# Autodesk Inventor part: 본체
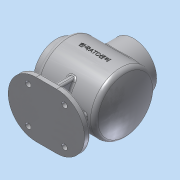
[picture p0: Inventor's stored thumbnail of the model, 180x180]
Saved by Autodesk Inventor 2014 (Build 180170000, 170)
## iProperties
Created: 2023-01
Part Number: 본체
Material: 알루미늄 6061
Document SubType Name: Modeling
Designer: dg
Density: 2.71 g/cm^3
Appearance: 알루미늄 - 평지
Mass: 1038.28 g
Surface Area: 1157.53 cm^2
Volume: 383.128 cm^3
Author: dg
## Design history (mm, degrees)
sketch "스케치1"
  geometry: L1 (0, 0)-(122, 0); L2 (0, 38)-(12, 38); L3 (12, 38)-(12, 50); L4 (12, 50)-(111.087, 50); L5 (0, 38)-(0, 27); L6 (0, 27)-(17, 27); L7 (17, 27)-(17, 45); L8 (17, 45)-(107.83, 45); A1 r 120 centre (2, 0) between (122, 0) and (111.087, 50); A2 r 115 centre (2, 0) between (117, 0) and (107.83, 45)
  constraints: 16 end point, 4 point on circle, 3 parallel, 2 centre point, 2 horizontal alignment, 2 perpendicular, 1 concentric, 1 horizontal, 1 point on line, 1 vertical alignment
  dimensions: "d0" = 122 distance of L1.start L1.end; "d1" = 54 diameter of L6 L1; "d2" = 76 diameter of L2 L1; "d3" = 100 diameter of L4 L1; "d4" = 17 distance of L5.end L6.end; "d5" = 110 horizontal distance of L1.end L3.end; "d6" = 120 radius of A1; "d7" = 90 diameter of L8 L1; "d8" = 5 radial gap between concentric circles of A1 A2
revolve "회전1" sketch "스케치1" stored, may be unused: angle "d9" = 90 deg
fillet "모깎기1" dims "d10" = 8
sketch "스케치2"
  geometry: C1 r 38 at (0, 0) reference; 1 further point
  constraints: 1 vertical alignment
  dimensions: "d11" = 32.5 distance of C1.centre point (0, 32.5)
hole "구멍1" sketch "스케치2" at (0, 32.5) diameter "d12" = 3.242; stored, may be unused: countersink angle "d16" = 90 deg, drill point angle "d18" = 118 deg; dims "d13" = 8, "d14" = 4, "d15" = 2, "d17" = 10
node "작업 평면1"
sketch "스케치3"
  geometry: L1 (0, 38)-(0, -38) reference; C1 r 38 at (-63, 0); A1 r 120 centre (-2, 0) between (-113.243, 45) and (-113.243, -45) reference; 2 further points
  constraints: 1 centre point, 1 horizontal alignment, 1 midpoint
  dimensions: "d23" = 76 diameter of C1; "d24" = 63 distance of point (0, 0) C1.centre
extrude "돌출1" join sketch "스케치3" stored distance "d25" = 10; taper "d26" = 0 deg
sketch "스케치4"
  geometry: C1 r 38 at (0, 0) reference; C2 r 27 at (0, 0); 1 further point
  constraints: 1 centre point, 1 coincident
  dimensions: "d27" = 54 diameter of C2
extrude "돌출2" cut sketch "스케치4" stored distance "d28" = 10; taper "d29" = 0 deg
chamfer "모따기1" distance "d30" = 1; stored, may be unused: second distance "d31" = 2, angle "d32" = 45 deg
sketch "스케치5"
  geometry: C1 r 38 at (0, 0) reference; 2 further points
  constraints: 1 vertical alignment
  dimensions: "d33" = 32.5 distance of C1.centre point (0, 32.5)
hole "구멍2" sketch "스케치5" at (0, 32.5) diameter "d34" = 3.242; stored, may be unused: countersink angle "d38" = 90 deg, drill point angle "d40" = 118 deg; dims "d35" = 8, "d36" = 4, "d37" = 2, "d39" = 10
fillet "모깎기2" dims "d44" = 3
chamfer "모따기2" distance "d45" = 1; stored, may be unused: second distance "d46" = 2, angle "d47" = 45 deg
fillet "모깎기3" dims "d48" = 3
node "작업 평면2"
sketch "스케치6"
  geometry: L1 (0, 38)-(0, -38) reference; L2 (-80, 46)-(-46, 46); L3 (-46, -46)-(-80, -46); L4 (-126, 0)-(0, 0); A1 r 46 centre (-46, 0) between (-46, -46) and (-46, 46); A2 r 46 centre (-80, 0) between (-80, 46) and (-80, -46); 2 further points
  constraints: 6 end point, 6 point on circle, 2 centre point, 2 perpendicular, 2 tangent, 1 coincident, 1 equal radius, 1 horizontal alignment, 1 midpoint, 1 parallel
  dimensions: "d50" = 92 distance between parallel lines of L3 L2; "d51" = 126 distance of L4.start point (0, 0)
extrude "돌출3" join sketch "스케치6" distance "d52" = 10; taper "d53" = 0 deg
sketch "스케치7"
  geometry: L1 (46, -46)-(80, -46) reference; L2 (80, 46)-(46, 46) reference; L3 (63, 46)-(63, -46); C1 r 4.5 at (33, 30); C2 r 4.5 at (33, -30); C3 r 4.5 at (93, -30); C4 r 4.5 at (93, 30); A1 r 46 centre (46, 0) between (46, 46) and (46, -46) reference; 1 further point
  constraints: 4 centre point, 3 equal radius, 2 end point, 2 horizontal alignment, 2 midpoint, 2 vertical alignment
  dimensions: "d54" = 60 distance of C4.centre C1.centre; "d55" = 60 distance of C2.centre C1.centre; "d56" = 30 vertical distance of A1.centre C2.centre; "d57" = 9 diameter of C1; "d58" = 30 distance from line of C4.centre L3
extrude "돌출4" cut sketch "스케치7" stored distance "d59" = 10; taper "d60" = 0 deg
sketch "스케치8"
  geometry: L1 (80, 46)-(46, 46) reference; L2 (58, 35)-(68, 35); L3 (68, 35)-(68, -35); L4 (68, -35)-(58, -35); L5 (58, -35)-(58, 35); A1 r 46 centre (46, 0) between (46, 46) and (46, -46) reference; 5 further points
  constraints: 8 end point, 3 midpoint, 2 parallel, 1 horizontal, 1 horizontal alignment, 1 perpendicular, 1 point on circle, 1 vertical alignment
  dimensions: "d61" = 10 distance of L2.start L2.end; "d62" = 70 distance of L4.end L2.start
extrude "돌출5" join sketch "스케치8" stored distance "d63" = 10; taper "d64" = 0 deg
sketch "스케치9"
  geometry: L1 (10.974, 32.5)-(10, 34.121) reference; L2 (10, 34.121)-(0, 34.121) reference; L3 (0, 34.121)-(0, 38) reference; L4 (0, 38)-(9, 38) reference; L5 (12, 41)-(12, 42) reference; L6 (20, 50)-(22, 50) reference; L7 (25, 53)-(25, 64) reference; L8 (25, 64)-(28.879, 64) reference; L9 (28.879, 64)-(28.879, 54) reference; L10 (28.879, 54)-(30.5, 53.026) reference; L11 (30.5, 53.026)-(32.121, 54) reference; L12 (32.121, 54)-(32.121, 64) reference; L13 (32.121, 64)-(35, 64) reference; L14 (35, 64)-(36, 63) reference; L15 (36, 63)-(36, 45) reference; L16 (36, 45)-(20, 45) reference; L17 (17, 42)-(17, 27) reference; L18 (17, 27)-(1, 27) reference; L19 (1, 27)-(0, 28) reference; L20 (0, 28)-(0, 30.879) reference; L21 (0, 30.879)-(10, 30.879) reference; L22 (10, 30.879)-(10.974, 32.5) reference; L23 (126, -70)-(126, -80) reference; L24 (126, -80)-(0, -80) reference; L25 (0, -80)-(0, -70) reference; L26 (0, -70)-(58, -70) reference; L27 (58, -70)-(58, -50) reference; L28 (58, -50)-(20, -50) reference; L29 (12, -42)-(12, -41) reference; L30 (9, -38)-(0, -38) reference; L31 (0, -38)-(0, -34.121) reference; L32 (0, -34.121)-(10, -34.121) reference; L33 (10, -34.121)-(10.974, -32.5) reference; L34 (10.974, -32.5)-(10, -30.879) reference; L35 (10, -30.879)-(0, -30.879) reference; L36 (0, -30.879)-(0, -28) reference; L37 (0, -28)-(1, -27) reference; L38 (1, -27)-(17, -27) reference; L39 (17, -27)-(17, -42) reference; L40 (20, -45)-(105.827, -45) reference; L41 (105.827, 45)-(90, 45) reference; L42 (90, 45)-(90, 63) reference; L43 (90, 63)-(91, 64) reference; L44 (91, 64)-(93.879, 64) reference; L45 (93.879, 64)-(93.879, 54) reference; L46 (93.879, 54)-(95.5, 53.026) reference; L47 (95.5, 53.026)-(97.121, 54) reference; L48 (97.121, 54)-(97.121, 64) reference; L49 (97.121, 64)-(101, 64) reference; L50 (101, 64)-(101, 53) reference; L51 (104, 50)-(105.827, 50) reference; L52 (105.827, -50)-(68, -50) reference; L53 (68, -50)-(68, -70) reference; L54 (68, -70)-(126, -70) reference; L55 (91, 64)-(35, 64) reference; L56 (63, -80)-(63, 64); L57 (23, -70)-(28.359, -50); A1 r 3 centre (9, 41) between (9, 38) and (12, 41) reference; A2 r 8 centre (20, 42) between (20, 50) and (12, 42) reference; A3 r 3 centre (20, 42) between (20, 45) and (17, 42) reference; A4 r 8 centre (20, -42) between (12, -42) and (20, -50) reference; A5 r 3 centre (9, -41) between (12, -41) and (9, -38) reference; A6 r 3 centre (20, -42) between (17, -42) and (20, -45) reference; A7 r 3 centre (105.827, -42) between (105.827, -45) and (108.608, -43.125) reference; A8 r 115 centre (2, 0) between (108.608, -43.125) and (108.608, 43.125) reference; A9 r 3 centre (105.827, 42) between (108.608, 43.125) and (105.827, 45) reference; A10 r 8 centre (105.827, 42) between (113.243, 45) and (105.827, 50) reference; A11 r 120 centre (2, 0) between (113.243, -45) and (113.243, 45) reference; A12 r 8 centre (105.827, -42) between (105.827, -50) and (113.243, -45) reference; 1 further point
  constraints: 4 end point, 2 midpoint, 2 point on line, 2 other
  dimensions: "d65" = 105 deg angle of L26 L57; "d66" = 40 horizontal distance of L56.start L57.start
feature "리브1" sketch "스케치9" dims "d67" = 1, "d68" = 10, "d69" = 0, "d70" = 0, "d71" = 1, "d72" = 1
sketch "스케치10"
  geometry: L1 (10, -34.121)-(10.974, -32.5) reference; L2 (10.974, -32.5)-(10, -30.879) reference; L3 (10, -30.879)-(0, -30.879) reference; L4 (0, -30.879)-(0, -28) reference; L5 (0, -28)-(1, -27) reference; L6 (1, -27)-(17, -27) reference; L7 (17, -27)-(17, -42) reference; L8 (20, -45)-(105.827, -45) reference; L9 (105.827, 45)-(90, 45) reference; L10 (90, 45)-(90, 63) reference; L11 (90, 63)-(91, 64) reference; L12 (91, 64)-(93.879, 64) reference; L13 (93.879, 64)-(93.879, 54) reference; L14 (93.879, 54)-(95.5, 53.026) reference; L15 (95.5, 53.026)-(97.121, 54) reference; L16 (97.121, 54)-(97.121, 64) reference; L17 (97.121, 64)-(101, 64) reference; L18 (101, 64)-(101, 53) reference; L19 (104, 50)-(105.827, 50) reference; L20 (105.827, -50)-(68, -50) reference; L21 (68, -50)-(68, -70) reference; L22 (68, -70)-(126, -70) reference; L23 (126, -70)-(126, -80) reference; L24 (126, -80)-(0, -80) reference; L25 (0, -80)-(0, -70) reference; L26 (0, -70)-(23, -70) reference; L27 (23, -70)-(28.359, -50) reference; L28 (28.359, -50)-(20, -50) reference; L29 (12, -42)-(12, -41) reference; L30 (9, -38)-(0, -38) reference; L31 (0, -38)-(0, -34.121) reference; L32 (0, -34.121)-(10, -34.121) reference; L33 (10.974, 32.5)-(10, 34.121) reference; L34 (10, 34.121)-(0, 34.121) reference; L35 (0, 34.121)-(0, 38) reference; L36 (0, 38)-(9, 38) reference; L37 (12, 41)-(12, 42) reference; L38 (20, 50)-(22, 50) reference; L39 (25, 53)-(25, 64) reference; L40 (25, 64)-(28.879, 64) reference; L41 (28.879, 64)-(28.879, 54) reference; L42 (28.879, 54)-(30.5, 53.026) reference; L43 (30.5, 53.026)-(32.121, 54) reference; L44 (32.121, 54)-(32.121, 64) reference; L45 (32.121, 64)-(35, 64) reference; L46 (35, 64)-(36, 63) reference; L47 (36, 63)-(36, 45) reference; L48 (36, 45)-(20, 45) reference; L49 (17, 42)-(17, 27) reference; L50 (17, 27)-(1, 27) reference; L51 (1, 27)-(0, 28) reference; L52 (0, 28)-(0, 30.879) reference; L53 (0, 30.879)-(10, 30.879) reference; L54 (10, 30.879)-(10.974, 32.5) reference; L55 (97.641, -50)-(103, -70); L56 (91, 64)-(35, 64) reference; L57 (63, 64)-(63, -80); A1 r 3 centre (20, -42) between (17, -42) and (20, -45) reference; A2 r 3 centre (105.827, -42) between (105.827, -45) and (108.608, -43.125) reference; A3 r 115 centre (2, 0) between (108.608, -43.125) and (108.608, 43.125) reference; A4 r 3 centre (105.827, 42) between (108.608, 43.125) and (105.827, 45) reference; A5 r 8 centre (105.827, 42) between (113.243, 45) and (105.827, 50) reference; A6 r 120 centre (2, 0) between (113.243, -45) and (113.243, 45) reference; A7 r 8 centre (105.827, -42) between (105.827, -50) and (113.243, -45) reference; A8 r 8 centre (20, -42) between (12, -42) and (20, -50) reference; A9 r 3 centre (9, -41) between (12, -41) and (9, -38) reference; A10 r 3 centre (9, 41) between (9, 38) and (12, 41) reference; A11 r 8 centre (20, 42) between (20, 50) and (12, 42) reference; A12 r 3 centre (20, 42) between (20, 45) and (17, 42) reference; 1 further point
  constraints: 4 end point, 2 midpoint, 2 point on line, 2 other
  dimensions: "d73" = 105 deg angle of L22 L55; "d74" = 40 horizontal distance of L55.end L57.end
feature "리브2" sketch "스케치10" dims "d75" = 1, "d76" = 10, "d77" = 0, "d78" = 0, "d79" = 1, "d80" = 1
fillet "모깎기4" dims "d81" = 3
fillet "모깎기5" dims "d82" = 3
node "작업 평면3"
sketch "스케치11"
  geometry: L1 (0, -38)-(0, 38) reference; L2 (97.5, -80)-(88.5, -80) reference; L3 (37.5, -80)-(28.5, -80) reference; L4 (37.5, -80)-(28.5, -80) reference; L5 (97.5, -80)-(88.5, -80) reference; L6 (46, -80)-(46, -80) reference; L7 (46, -80)-(80, -80) reference; L8 (80, -80)-(80, -80) reference; L9 (80, -80)-(46, -80) reference; L10 (80, -80)-(126, -80) reference; 2 further points
  constraints: 1 other
  dimensions: "d84" = 80 distance from line of L10 point (63, 0); "d85" = 63 distance from line of L1 point (63, 0)
feature "엠보싱1" sketch "스케치11" dims "d0" = 122, "d1" = 54, "d2" = 76, "d3" = 100, "d4" = 17, "d5" = 110, "d6" = 120, "d7" = 90, "d8" = 5, "d13" = 8, "d86" = 0.5, "d87" = 0
node "솔리드1"
pattern_circular "원형 패턴1" dims angle "d20" = 360 deg
pattern_circular "원형 패턴2" dims angle "d42" = 360 deg
node "투영된 루프1"
node "절단 모서리 투영1"
node "절단 모서리 투영2"
other parameters: "d22" = 64, "d83" = 50.5
